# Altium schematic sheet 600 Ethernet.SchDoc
size Letter; Organization: Toradex Solutions Inc.; Address1: 6415 Northwest Drive; Address2: Mississauga, ON, L4V 1X1; Address3: Canada
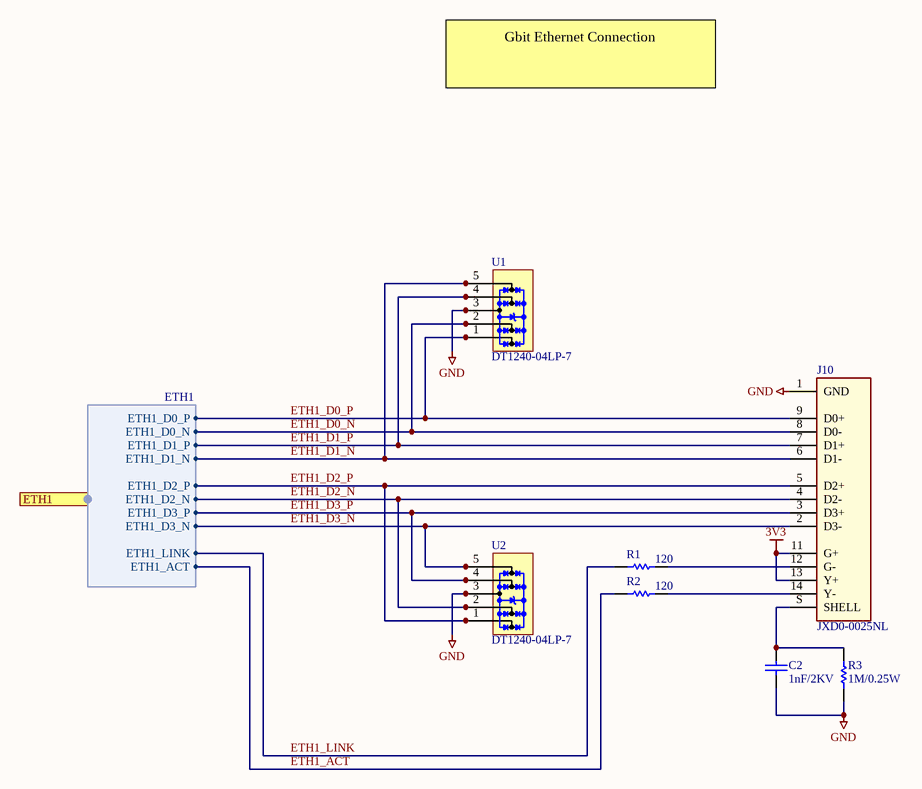
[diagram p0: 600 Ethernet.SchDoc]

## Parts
C2  value 1nF/2KV  [C/1206]  (hidden comment: 0567-Cap-1206-1nF/2KV)
J10  JXD0-0025NL  [PULSE_JXD0-0025NL]
R1  value 120  [R0402_RESC1005L]  (hidden comment: 1552-Res-0402-120)
R2  value 120  [R0402_RESC1005L]  (hidden comment: 1552-Res-0402-120)
R3  value 1M/0.25W  [R/1206]  (hidden comment: 1860-Res-1206-1M-5%-0.25W)
U1  DT1240-04LP-7  [10-UFDFN]
U2  DT1240-04LP-7  [10-UFDFN]

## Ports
ETH1 (harness ETH1)

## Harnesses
ETH1: ETH1_D0_P, ETH1_D0_N, ETH1_D1_N, ETH1_D1_P, ETH1_LINK, ETH1_ACT, ETH1_D2_P, ETH1_D2_N, ETH1_D3_N, ETH1_D3_P

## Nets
3V3: J10.11(G+) J10.13(Y+)
GND: C2.1 J10.1(GND) R3.2 U1.3(GND) U1.8(GND) U2.3(GND) U2.8(GND)
ETH1_ACT: R2.2 ; port ETH1.ETH1_ACT
ETH1_D0_N: J10.8(D0-) U1.2(IO2) U1.9(NC) ; port ETH1.ETH1_D0_N
ETH1_D0_P: J10.9(D0+) U1.1(IO1) U1.10(NC) ; port ETH1.ETH1_D0_P
ETH1_D1_N: J10.6(D1-) U1.5(IO4) U1.6(NC) ; port ETH1.ETH1_D1_N
ETH1_D1_P: J10.7(D1+) U1.4(IO3) U1.7(NC) ; port ETH1.ETH1_D1_P
ETH1_D2_N: J10.4(D2-) U2.2(IO2) U2.9(NC) ; port ETH1.ETH1_D2_N
ETH1_D2_P: J10.5(D2+) U2.1(IO1) U2.10(NC) ; port ETH1.ETH1_D2_P
ETH1_D3_N: J10.2(D3-) U2.5(IO4) U2.6(NC) ; port ETH1.ETH1_D3_N
ETH1_D3_P: J10.3(D3+) U2.4(IO3) U2.7(NC) ; port ETH1.ETH1_D3_P
ETH1_LINK: R1.2 ; port ETH1.ETH1_LINK
NetC2_2: C2.2 J10.S(SHELL) R3.1
NetJ10_12: J10.12(G-) R1.1
NetJ10_14: J10.14(Y-) R2.1

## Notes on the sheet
- Gbit Ethernet Connection

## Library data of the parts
C2 = 0567-Cap-1206-1nF/2KV: CAP CER 1000PF 2KV X7R 1206; Mfr: Johanson Dielectrics Inc.; MfrNo: 202R18W102KV4E; PN: 567; Alt: 478-2956-1-ND; Alt2: 399-4819-1-ND
J10 = 1380-Conn-RJ45-GBe: (-40 to 85 DegC) CONN MAGJACK 1PORT 1000 BASE-T Isolated Taps; Mfr: Pulse; PN: 1380
R1 R2 = 1552-Res-0402-120: (-55 to 155 DegC AEC) RES 120 OHM 1% 1/16W 100ppm 0402; MfrNo: RMCF0402FT120R; Mfr: Stackpole Electronics; PN: 1552; Alt: AC0402FR-07120RL,CRGCQ0402F120R
R3 = 1860-Res-1206-1M-5%-0.25W: (-55 to 155 DegC) RES SMD 1M OHM 5% 0.25W 10ppm 1206; Mfr: TE Connectivity; MfrNo: CRGCQ1206J1M0; PN: 1860; Alt: RMCF1206JT1M00, RMCF1206JG1M00, CR1206-JW-105ELF
U1 U2 = 1657-DT1240-04LP-7: (-55 to 85 DegC) IC TVS DIODE 4ch Vrm:5.5V Vcl:11V@5.5A 10-UFDFN 0.5mm; Mfr: Diodes; PN: 1657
